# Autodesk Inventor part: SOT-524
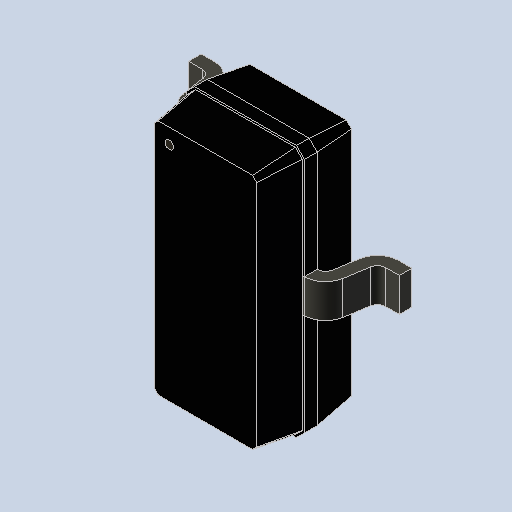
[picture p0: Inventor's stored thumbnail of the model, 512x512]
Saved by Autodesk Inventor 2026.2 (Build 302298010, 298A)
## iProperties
Created: 2026-10
Part Number: SOT-524
Material: Générique
Document SubType Name: Modeling
Designer: mel
Density: 1 g/cm^3
Appearance: Par défaut
Author: mel
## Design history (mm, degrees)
feature "Base1"
node "Solide1"
